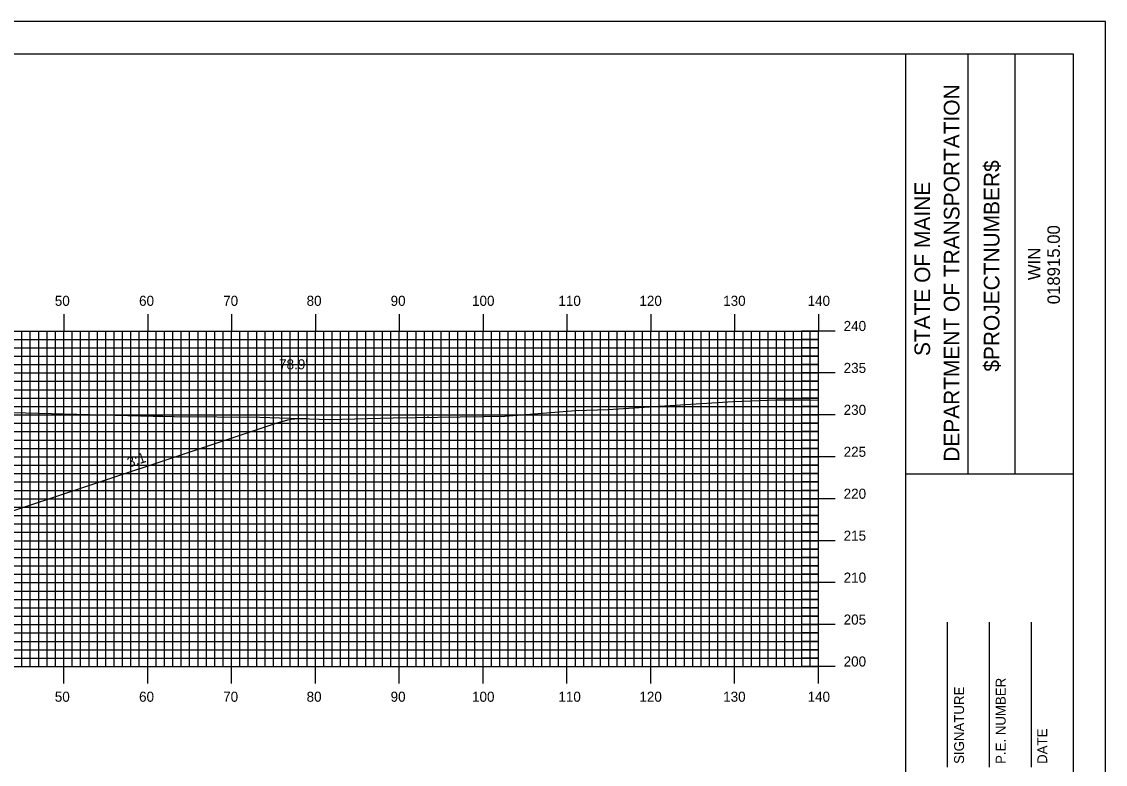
# Model space of a CAD drawing. Extents: x 1801536 to 1801879, y 442591 to 442811.
# Drawn here: x 1801746.5 to 1801875.8, y 442722 to 442810.5 of the extents above; entities that cross this region are included whole.
import ezdxf

# ---------------------------------------------------------------- set-up
doc = ezdxf.new("R2010")
doc.units = 0
for name, color, linetype in [('ANNOTATION', 7, 'Continuous'), ('BORDER', 7, 'Continuous'), ('D_Roadway_SlopeLines', 7, 'Continuous'), ('D_Text_Standard', 7, 'Continuous'), ('H_V ANNOTATION', 7, 'Continuous'), ('M_Utilities_Pole', 7, 'Continuous'), ('MAJOR', 7, 'Continuous'), ('MINOR', 7, 'Continuous'), ('PLOT BOUNDARY', 7, 'Continuous'), ('S_Roadway_Centerline', 7, 'Continuous')]:
    doc.layers.add(name, color=color, linetype=linetype)

msp = doc.modelspace()

# ---------------------------------------------------------------- linework, layer by layer
at = {"layer": 'BORDER'}
for p, q in [((1801851.98, 442596.67), (1801851.98, 442806.67)), ((1801859.43, 442756.66), (1801859.43, 442806.66)), ((1801865.02, 442756.66), (1801865.02, 442806.66)), ((1801851.98, 442756.65), (1801871.98, 442756.65)), ((1801856.98, 442721.67), (1801856.98, 442738.97)), ((1801861.98, 442721.67), (1801861.98, 442738.97)), ((1801866.98, 442721.67), (1801866.98, 442738.97))]:
    msp.add_line(p, q, dxfattribs=at)
msp.add_lwpolyline([(1801551.98, 442596.67), (1801871.98, 442596.67), (1801871.98, 442806.67), (1801551.98, 442806.67)], close=True, dxfattribs=at)
at = {"layer": 'D_Roadway_SlopeLines'}
msp.add_line((1801776.98, 442762.69), (1801744.14, 442751.74), dxfattribs=at)
msp.add_arc((1801780.26, 442752.86), 10.36, 88.8449, 108.4349, dxfattribs=at)
at = {"layer": 'M_Utilities_Pole'}
msp.add_line((1801794.98, 442763.5), (1801794.98, 442763.48), dxfattribs=at)
msp.add_circle((1801794.98, 442763.49), 0.00417, dxfattribs=at)
at = {"layer": 'MAJOR'}
for p, q in [((1801751.58, 442775.67), (1801751.58, 442773.67)), ((1801761.58, 442775.67), (1801761.58, 442773.67)), ((1801771.58, 442775.67), (1801771.58, 442773.67)), ((1801781.58, 442775.67), (1801781.58, 442773.67)), ((1801791.58, 442775.67), (1801791.58, 442773.67)), ((1801801.58, 442775.67), (1801801.58, 442773.67)), ((1801811.58, 442775.67), (1801811.58, 442773.67)), ((1801821.58, 442775.67), (1801821.58, 442773.67)), ((1801831.58, 442775.67), (1801831.58, 442773.67)), ((1801841.58, 442775.67), (1801841.58, 442773.67)), ((1801561.58, 442773.67), (1801841.58, 442773.67)), ((1801561.58, 442773.67), (1801841.58, 442773.67)), ((1801751.58, 442733.67), (1801751.58, 442773.67)), ((1801761.58, 442733.67), (1801761.58, 442773.67)), ((1801771.58, 442733.67), (1801771.58, 442773.67)), ((1801781.58, 442733.67), (1801781.58, 442773.67)), ((1801791.58, 442733.67), (1801791.58, 442773.67)), ((1801801.58, 442733.67), (1801801.58, 442773.67)), ((1801811.58, 442733.67), (1801811.58, 442773.67)), ((1801821.58, 442733.67), (1801821.58, 442773.67)), ((1801831.58, 442733.67), (1801831.58, 442773.67)), ((1801843.58, 442773.67), (1801839.57, 442773.67)), ((1801841.58, 442733.67), (1801841.58, 442773.67)), ((1801841.58, 442733.67), (1801841.58, 442773.67)), ((1801561.58, 442768.67), (1801841.58, 442768.67)), ((1801843.58, 442768.67), (1801839.57, 442768.67)), ((1801561.58, 442763.67), (1801841.58, 442763.67)), ((1801843.58, 442763.67), (1801839.57, 442763.67)), ((1801561.58, 442758.67), (1801841.58, 442758.67)), ((1801843.58, 442758.67), (1801839.57, 442758.67)), ((1801561.58, 442753.67), (1801841.58, 442753.67)), ((1801843.58, 442753.67), (1801839.57, 442753.67)), ((1801561.58, 442748.67), (1801841.58, 442748.67)), ((1801843.58, 442748.67), (1801839.57, 442748.67)), ((1801561.58, 442743.67), (1801841.58, 442743.67)), ((1801843.58, 442743.67), (1801839.57, 442743.67)), ((1801561.58, 442738.67), (1801841.58, 442738.67)), ((1801843.58, 442738.67), (1801839.57, 442738.67)), ((1801561.58, 442733.67), (1801841.58, 442733.67)), ((1801561.58, 442733.67), (1801841.58, 442733.67)), ((1801751.58, 442731.66), (1801751.58, 442733.67)), ((1801761.58, 442731.66), (1801761.58, 442733.67)), ((1801771.58, 442731.66), (1801771.58, 442733.67)), ((1801781.58, 442731.66), (1801781.58, 442733.67)), ((1801791.58, 442731.66), (1801791.58, 442733.67)), ((1801801.58, 442731.66), (1801801.58, 442733.67)), ((1801811.58, 442731.66), (1801811.58, 442733.67)), ((1801821.58, 442731.66), (1801821.58, 442733.67)), ((1801831.58, 442731.66), (1801831.58, 442733.67)), ((1801843.58, 442733.67), (1801839.57, 442733.67)), ((1801841.58, 442731.66), (1801841.58, 442733.67))]:
    msp.add_line(p, q, dxfattribs=at)
at = {"layer": 'MINOR'}
for p, q in [((1801561.58, 442772.67), (1801841.58, 442772.67)), ((1801746.58, 442733.67), (1801746.58, 442773.67)), ((1801747.58, 442733.67), (1801747.58, 442773.67)), ((1801748.58, 442733.67), (1801748.58, 442773.67)), ((1801749.58, 442733.67), (1801749.58, 442773.67)), ((1801750.58, 442733.67), (1801750.58, 442773.67)), ((1801752.58, 442733.67), (1801752.58, 442773.67)), ((1801753.58, 442733.67), (1801753.58, 442773.67)), ((1801754.58, 442733.67), (1801754.58, 442773.67)), ((1801755.58, 442733.67), (1801755.58, 442773.67)), ((1801756.58, 442733.67), (1801756.58, 442773.67)), ((1801757.58, 442733.67), (1801757.58, 442773.67)), ((1801758.58, 442733.67), (1801758.58, 442773.67)), ((1801759.58, 442733.67), (1801759.58, 442773.67)), ((1801760.58, 442733.67), (1801760.58, 442773.67)), ((1801762.58, 442733.67), (1801762.58, 442773.67)), ((1801763.58, 442733.67), (1801763.58, 442773.67)), ((1801764.58, 442733.67), (1801764.58, 442773.67)), ((1801765.58, 442733.67), (1801765.58, 442773.67)), ((1801766.58, 442733.67), (1801766.58, 442773.67)), ((1801767.58, 442733.67), (1801767.58, 442773.67)), ((1801768.58, 442733.67), (1801768.58, 442773.67)), ((1801769.58, 442733.67), (1801769.58, 442773.67)), ((1801770.58, 442733.67), (1801770.58, 442773.67)), ((1801772.58, 442733.67), (1801772.58, 442773.67)), ((1801773.58, 442733.67), (1801773.58, 442773.67)), ((1801774.58, 442733.67), (1801774.58, 442773.67)), ((1801775.58, 442733.67), (1801775.58, 442773.67)), ((1801776.58, 442733.67), (1801776.58, 442773.67)), ((1801777.58, 442733.67), (1801777.58, 442773.67)), ((1801778.58, 442733.67), (1801778.58, 442773.67)), ((1801779.58, 442733.67), (1801779.58, 442773.67)), ((1801780.58, 442733.67), (1801780.58, 442773.67)), ((1801782.58, 442733.67), (1801782.58, 442773.67)), ((1801783.58, 442733.67), (1801783.58, 442773.67)), ((1801784.58, 442733.67), (1801784.58, 442773.67)), ((1801785.58, 442733.67), (1801785.58, 442773.67)), ((1801786.58, 442733.67), (1801786.58, 442773.67)), ((1801787.58, 442733.67), (1801787.58, 442773.67)), ((1801788.58, 442733.67), (1801788.58, 442773.67)), ((1801789.58, 442733.67), (1801789.58, 442773.67)), ((1801790.58, 442733.67), (1801790.58, 442773.67)), ((1801792.58, 442733.67), (1801792.58, 442773.67)), ((1801793.58, 442733.67), (1801793.58, 442773.67)), ((1801794.58, 442733.67), (1801794.58, 442773.67)), ((1801795.58, 442733.67), (1801795.58, 442773.67)), ((1801796.58, 442733.67), (1801796.58, 442773.67)), ((1801797.58, 442733.67), (1801797.58, 442773.67)), ((1801798.58, 442733.67), (1801798.58, 442773.67)), ((1801799.58, 442733.67), (1801799.58, 442773.67)), ((1801800.58, 442733.67), (1801800.58, 442773.67)), ((1801802.58, 442733.67), (1801802.58, 442773.67)), ((1801803.58, 442733.67), (1801803.58, 442773.67)), ((1801804.58, 442733.67), (1801804.58, 442773.67)), ((1801805.58, 442733.67), (1801805.58, 442773.67)), ((1801806.58, 442733.67), (1801806.58, 442773.67)), ((1801807.58, 442733.67), (1801807.58, 442773.67)), ((1801808.58, 442733.67), (1801808.58, 442773.67)), ((1801809.58, 442733.67), (1801809.58, 442773.67)), ((1801810.58, 442733.67), (1801810.58, 442773.67)), ((1801812.58, 442733.67), (1801812.58, 442773.67)), ((1801813.58, 442733.67), (1801813.58, 442773.67)), ((1801814.58, 442733.67), (1801814.58, 442773.67)), ((1801815.58, 442733.67), (1801815.58, 442773.67)), ((1801816.58, 442733.67), (1801816.58, 442773.67)), ((1801817.58, 442733.67), (1801817.58, 442773.67)), ((1801818.58, 442733.67), (1801818.58, 442773.67)), ((1801819.58, 442733.67), (1801819.58, 442773.67)), ((1801820.58, 442733.67), (1801820.58, 442773.67)), ((1801822.58, 442733.67), (1801822.58, 442773.67)), ((1801823.58, 442733.67), (1801823.58, 442773.67)), ((1801824.58, 442733.67), (1801824.58, 442773.67)), ((1801825.58, 442733.67), (1801825.58, 442773.67)), ((1801826.58, 442733.67), (1801826.58, 442773.67)), ((1801827.58, 442733.67), (1801827.58, 442773.67)), ((1801828.58, 442733.67), (1801828.58, 442773.67)), ((1801829.58, 442733.67), (1801829.58, 442773.67)), ((1801830.58, 442733.67), (1801830.58, 442773.67)), ((1801832.58, 442733.67), (1801832.58, 442773.67)), ((1801833.58, 442733.67), (1801833.58, 442773.67)), ((1801834.58, 442733.67), (1801834.58, 442773.67)), ((1801835.58, 442733.67), (1801835.58, 442773.67)), ((1801836.58, 442733.67), (1801836.58, 442773.67)), ((1801837.58, 442733.67), (1801837.58, 442773.67)), ((1801838.58, 442733.67), (1801838.58, 442773.67)), ((1801841.58, 442772.67), (1801839.57, 442772.67)), ((1801839.58, 442733.67), (1801839.58, 442773.67)), ((1801840.58, 442733.67), (1801840.58, 442773.67)), ((1801561.58, 442771.67), (1801841.58, 442771.67)), ((1801841.58, 442771.67), (1801839.57, 442771.67)), ((1801561.58, 442770.67), (1801841.58, 442770.67)), ((1801841.58, 442770.67), (1801839.57, 442770.67)), ((1801561.58, 442769.67), (1801841.58, 442769.67)), ((1801841.58, 442769.67), (1801839.57, 442769.67)), ((1801561.58, 442767.67), (1801841.58, 442767.67)), ((1801841.58, 442767.67), (1801839.57, 442767.67)), ((1801561.58, 442766.67), (1801841.58, 442766.67)), ((1801841.58, 442766.67), (1801839.57, 442766.67)), ((1801561.58, 442765.67), (1801841.58, 442765.67)), ((1801841.58, 442765.67), (1801839.57, 442765.67)), ((1801561.58, 442764.67), (1801841.58, 442764.67)), ((1801841.58, 442764.67), (1801839.57, 442764.67)), ((1801561.58, 442762.67), (1801841.58, 442762.67)), ((1801841.58, 442762.67), (1801839.57, 442762.67)), ((1801561.58, 442761.67), (1801841.58, 442761.67)), ((1801841.58, 442761.67), (1801839.57, 442761.67)), ((1801561.58, 442760.67), (1801841.58, 442760.67)), ((1801561.58, 442759.67), (1801841.58, 442759.67)), ((1801841.58, 442760.67), (1801839.57, 442760.67)), ((1801841.58, 442759.67), (1801839.57, 442759.67)), ((1801561.58, 442757.67), (1801841.58, 442757.67)), ((1801841.58, 442757.67), (1801839.57, 442757.67)), ((1801561.58, 442756.67), (1801841.58, 442756.67)), ((1801841.58, 442756.67), (1801839.57, 442756.67)), ((1801561.58, 442755.67), (1801841.58, 442755.67)), ((1801561.58, 442754.67), (1801841.58, 442754.67)), ((1801841.58, 442755.67), (1801839.57, 442755.67)), ((1801841.58, 442754.67), (1801839.57, 442754.67)), ((1801561.58, 442752.67), (1801841.58, 442752.67)), ((1801841.58, 442752.67), (1801839.57, 442752.67)), ((1801561.58, 442751.67), (1801841.58, 442751.67)), ((1801561.58, 442750.67), (1801841.58, 442750.67)), ((1801841.58, 442751.67), (1801839.57, 442751.67)), ((1801841.58, 442750.67), (1801839.57, 442750.67)), ((1801561.58, 442749.67), (1801841.58, 442749.67)), ((1801841.58, 442749.67), (1801839.57, 442749.67)), ((1801561.58, 442747.67), (1801841.58, 442747.67)), ((1801841.58, 442747.67), (1801839.57, 442747.67)), ((1801561.58, 442746.67), (1801841.58, 442746.67)), ((1801561.58, 442745.67), (1801841.58, 442745.67)), ((1801841.58, 442746.67), (1801839.57, 442746.67)), ((1801841.58, 442745.67), (1801839.57, 442745.67)), ((1801561.58, 442744.67), (1801841.58, 442744.67)), ((1801841.58, 442744.67), (1801839.57, 442744.67)), ((1801561.58, 442742.67), (1801841.58, 442742.67)), ((1801561.58, 442741.67), (1801841.58, 442741.67)), ((1801841.58, 442742.67), (1801839.57, 442742.67)), ((1801841.58, 442741.67), (1801839.57, 442741.67)), ((1801561.58, 442740.67), (1801841.58, 442740.67)), ((1801841.58, 442740.67), (1801839.57, 442740.67)), ((1801561.58, 442739.67), (1801841.58, 442739.67)), ((1801841.58, 442739.67), (1801839.57, 442739.67)), ((1801561.58, 442737.67), (1801841.58, 442737.67)), ((1801561.58, 442736.67), (1801841.58, 442736.67)), ((1801841.58, 442737.67), (1801839.57, 442737.67)), ((1801841.58, 442736.67), (1801839.57, 442736.67)), ((1801561.58, 442735.67), (1801841.58, 442735.67)), ((1801841.58, 442735.67), (1801839.57, 442735.67)), ((1801561.58, 442734.67), (1801841.58, 442734.67)), ((1801841.58, 442734.67), (1801839.57, 442734.67))]:
    msp.add_line(p, q, dxfattribs=at)
at = {"layer": 'PLOT BOUNDARY'}
msp.add_lwpolyline([(1801535.79, 442590.55), (1801875.79, 442590.55), (1801875.79, 442810.55), (1801535.79, 442810.55)], close=True, dxfattribs=at)
at = {"layer": 'S_Roadway_Centerline'}
msp.add_lwpolyline([(1801740.84, 442764.07), (1801750.1, 442763.83), (1801762.24, 442763.5), (1801763.37, 442763.5), (1801764.73, 442763.47), (1801774.97, 442763.39), (1801783.21, 442763.13), (1801790.85, 442763.3), (1801804.16, 442763.51), (1801812.64, 442764.21), (1801816.49, 442764.31), (1801825.72, 442764.91), (1801831.4, 442765.25), (1801836.63, 442765.45), (1801837.31, 442765.46), (1801840.64, 442765.45), (1801841.58, 442765.44)], dxfattribs=at)

# ---------------------------------------------------------------- texts
at = {"layer": 'ANNOTATION'}
msp.add_text('3:1', height=1.2, rotation=18.4349, dxfattribs=at).set_placement((1801759.36, 442757.38))
at = {"layer": 'BORDER'}
for s, height, p in [('DEPARTMENT OF TRANSPORTATION', 1.8635, (1801858.39, 442758.08)), ('$PROJECTNUMBER$', 1.8635, (1801863.16, 442768.82)), ('STATE OF MAINE', 1.8635, (1801854.89, 442770.69)), ('018915.00', 1.491, (1801870.37, 442776.86)), ('WIN', 1.491, (1801868.05, 442779.73)), ('P.E. NUMBER', 1.1811, (1801863.9, 442722.06)), ('SIGNATURE', 1.181, (1801858.94, 442722.06)), ('DATE', 1.181, (1801868.86, 442722.06))]:
    msp.add_text(s, height=height, rotation=90, dxfattribs=at).set_placement(p)
at = {"layer": 'D_Text_Standard'}
msp.add_text("78.9'", height=1.2, dxfattribs=at).set_placement((1801777.25, 442769.1))
at = {"layer": 'H_V ANNOTATION'}
for s, p in [('50', (1801750.5, 442776.67)), ('60', (1801760.55, 442776.67)), ('70', (1801770.58, 442776.67)), ('80', (1801780.53, 442776.67)), ('90', (1801790.55, 442776.67)), ('100', (1801800.26, 442776.67)), ('110', (1801810.56, 442776.67)), ('120', (1801820.22, 442776.67)), ('130', (1801830.21, 442776.67)), ('140', (1801840.28, 442776.67)), ('240', (1801844.58, 442773.67)), ('235', (1801844.58, 442768.67)), ('230', (1801844.58, 442763.67)), ('225', (1801844.58, 442758.67)), ('220', (1801844.58, 442753.67)), ('215', (1801844.58, 442748.67)), ('210', (1801844.58, 442743.67)), ('205', (1801844.58, 442738.67)), ('200', (1801844.58, 442733.67)), ('50', (1801750.5, 442729.47)), ('60', (1801760.55, 442729.47)), ('70', (1801770.58, 442729.47)), ('80', (1801780.53, 442729.47)), ('90', (1801790.55, 442729.47)), ('100', (1801800.26, 442729.47)), ('110', (1801810.56, 442729.47)), ('120', (1801820.22, 442729.47)), ('130', (1801830.21, 442729.47)), ('140', (1801840.28, 442729.47))]:
    msp.add_text(s, height=1.2, dxfattribs=at).set_placement(p)

doc.saveas('drawing.dxf')
